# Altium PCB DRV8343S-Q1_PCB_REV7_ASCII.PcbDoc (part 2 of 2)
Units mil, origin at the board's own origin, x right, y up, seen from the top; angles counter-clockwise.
Board outline 3860 x 4000 mil, 4 copper layers (Top Layer, POWER, GND, Bottom Layer), stack 40 mil thick; 195 components, 122 nets, 548 pads, 642 vias.
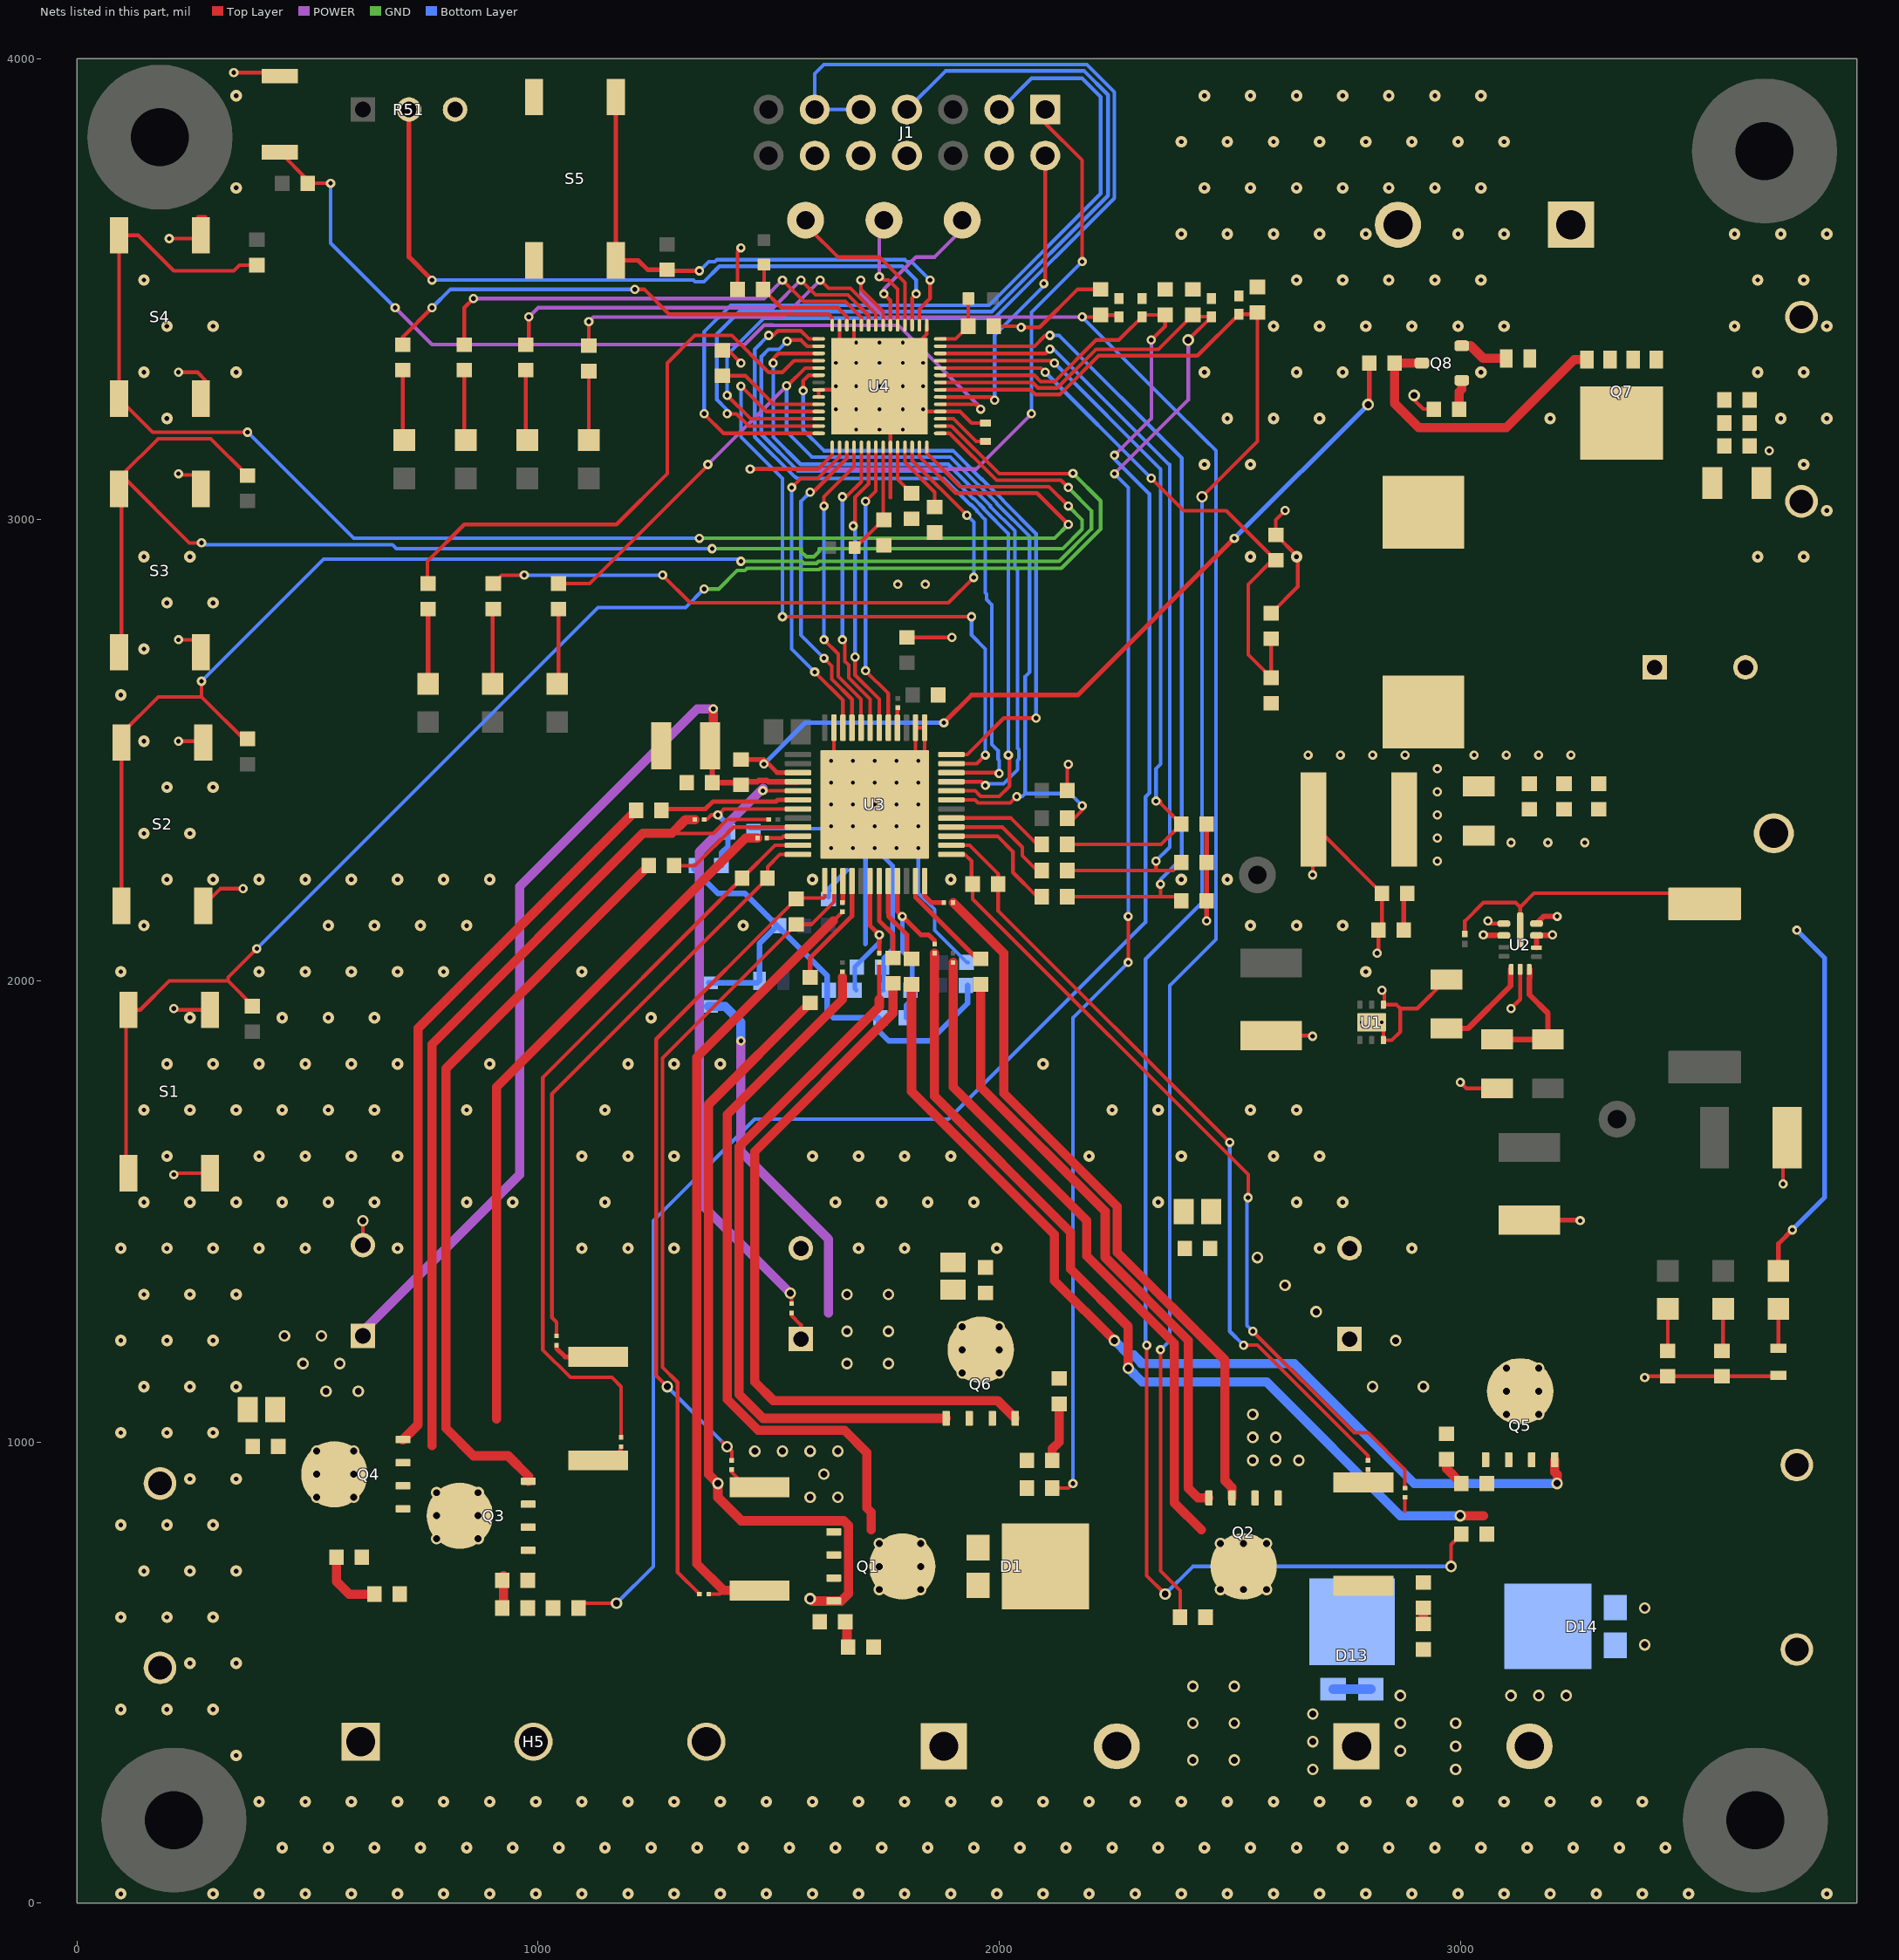
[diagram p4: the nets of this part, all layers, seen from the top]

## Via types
v1: diameter 25, hole 10, Top Layer to Bottom Layer, tented both sides, 315 vias
v2: diameter 20, hole 10, Top Layer to Bottom Layer, 173 vias
v3: diameter 25, hole 15, Top Layer to Bottom Layer, 106 vias
v4: diameter 19.68, hole 7.87, Top Layer to Bottom Layer, 32 vias
v5: diameter 19.68, hole 7.87, Top Layer to Bottom Layer, tented both sides, 16 vias

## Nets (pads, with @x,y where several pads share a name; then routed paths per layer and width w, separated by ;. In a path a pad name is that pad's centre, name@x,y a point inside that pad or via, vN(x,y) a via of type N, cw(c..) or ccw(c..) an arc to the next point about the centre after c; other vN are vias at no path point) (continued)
ENABLE: U3.36 U4.34 | length 1360.4
  Top Layer w8: v2(1574.88,3280) 1574.88,3301.59 1586.92,3313.62 U4.34@1608.5,3313.62 ; U3.36@1896.34,2491.02 1931.02,2491.02 2010,2570 v2(2080,2570)
  Bottom Layer w8: v2(1574.88,3280) 1574.88,3195.12 1620,3150 1900,3150 1961.5,3088.5 1962.52,3088.5 2008.5,3042.52 2008.5,3041.5 2080,2970 v2(2080,2570)
FB: R17.2 R18.1 U2.7 | length 278.7
  Top Layer w12: R17.2@3080,1873.15 R18.1@3190,1873.15 3190,1930 3150,1970 3150,2006.68 3150.92,2007.6 U2.7@3150.92,2024.88
GH_A: R29.1 U3.6 | length 305.5
  Top Layer w10: R29.1@1267.56,2370 1270.32,2372.76 1362.76,2372.76 1379,2389 1515.87,2389 1519.47,2392.6 U3.6@1563.66,2392.6
GH_B: R23.1 U3.19 | length 178.9
  Top Layer w10: U3.19@1739.84,2216.42 1739.84,2130.16 1770,2100 R23.1@1770,2050
GH_C: R21.1 U3.20 | length 189.7
  Top Layer w10: U3.20@1759.53,2216.42 1759.53,2147.67 1760,2147.2 1760,2140.31 1800,2100 1800,2057.56 R21.1@1810,2047.56
GL_A: R26.1 U3.9 | length 303.1
  Top Layer w8: R26.1@1295.12,2250 1340,2250 1423.54,2333.54 U3.9@1563.66,2333.54
GL_B: R20.1 U3.16 | length 246.5
  Top Layer w10: R20.1@1590,2007.56 1590,2050 1680.79,2140.79 U3.16@1680.79,2216.42
GL_C: R22.1 U3.23 | length 231.9
  Top Layer w10: U3.23@1818.58,2216.42 1818.58,2181.42 1952.44,2047.56 R22.1@1960,2047.56
GND: C7.2 C8.2 C9.2 C10.2 C11.2 C12.2 C13.2 C14.2 C15.2 C16.2 C17.2 C18.2 C19.2 C21.2 C23.2 C24.2 C27.2 C28.2 C29.2 C30.2 C31.2 C32.2 C33.2 C34.2 C36.2 C37.2 C38.2 C40.2 C41.2 C42.2 C43.2 C44.2 C45.2 C46.2 C47.2 C48.2 C49.2 C50.2 C51.2 C52.2 C53.2 C54.2 C55.2 C56.2 D14.1 D14.2 GND1.1 GND1.2 GND2.1 GND2.2 GND3.1 GND3.2 H5.1 H6.2 J1.4 J1.8 J1.10 J1.12 NT3.2 NT4.2 NT6.2 R6.1 R7.1 R11.1 R14.1 R15.1 R16.2 R17.1 R32.1 R36.1 R38.2 R44.1 R45.1 R46.1 R47.1 R51.3 R53.1 R56.1 R57.1 R59.1 R61.1 S1.3 S1.4 S2.3 S2.4 S3.3 S3.4 S4.3 S4.4 S5.3 S5.4 S6.2 U1.3 U1.4 U1.7@2807.72,1910 U2.1 U2.6 U2.11 U3.37 U3.38 U3.47 U3.49@1730,2382.76 U4.4 U4.15 U4.25 U4.27 U4.36 U4.37 U4.51 U4.57 | length 5859.3
  Top Layer w8: v2(200,3610) 261.42,3610 S4.4@268.58,3617.17 ; v2(210,1580) 212.83,1582.83 S1.3@288.58,1582.83 ; v2(210,1940) 212.83,1937.17 S1.4@288.58,1937.17 ; v2(220,2520) 270.75,2520 S2.4@273.58,2517.17 ; v2(220,2740) 270.75,2740 S3.3@273.58,2742.83 ; v2(220,3100) 222.83,3097.17 S3.4@273.58,3097.17 ; v2@222.83,3322.83 v2(220,3320) 261.42,3320 278.58,3302.83 ; 262.83,3657.17 278.58,3657.17 ; S2.3@273.58,2162.83 310.75,2200 v2(360,2200) ; v2(340,3970) 432.68,3970 S6.2@440,3962.68 ; C11.2@620,1426.85 v3(620,1480) ; C50.2@1400,3367.56 1412.44,3367.56 v2(1440,3340) ; 1420,934 1451.8,902.2 R6.1@1480,902.2 ; C56.2@1432.44,3500 1432.44,3582.44 v2(1440,3590) ; U4.37@1608.5,3266.38 U4.36@1608.5,3282.13 1638.03,3282.13 v4(1645.91,3290) ; v5(1635.51,2477.24) 1641.42,2483.15 U3.47@1641.42,2549.09 ; U4.57@1653.78,3376.61 U4.27@1653.78,3421.89 ; U4.25@1685.28,3421.89 1685.28,3389.21 v4(1690,3384.49) ; v4(1730,2382.76) v4(1777.24,2430) v5(1824.49,2477.24) 1838.27,2491.02 U3.37@1838.27,2549.09 U3.38@1818.58,2549.09 U3.49@1818.58,2483.15 ; v4(1740.39,3290) 1740.39,3300.39 1842.76,3402.76 U4.15@1842.76,3421.89 ; 1764.02,3048.43 U4.51@1764.02,3158.11 U4.57@1764.02,3266.38 ; C41.2@1800,2745.12 1857.56,2745.12 ; v4(1834.88,3239.61) 1839.61,3234.88 U4.4@1872.28,3234.88 1915.12,3234.88 1940,3210 C47.2@1970,3210 ; 1850,2745.12 v2(1897.56,2745.12) ; C51.2@1987.95,3420 2050,3420 v2(2047.5,3417.5) 2087.5,3417.5 2169.68,3499.68 R44.1@2220,3499.68 ; C34.2@2147.56,2412.76 2147.56,2467.56 v2(2150,2470) ; C18.2@2590,1881.26 2678.74,1881.26 v2(2680,1880) ; R32.1@2590,2797.56 2647.56,2855.12 2647.56,2920 C42.2@2600,2967.56 2600,3000 v2(2620,3020) ; v2(2680,2230) 2680,2348.43 C28.2@2681.57,2350 2681.57,2338.43 C24.2@2830,2190 2830,2117.56 C21.2@2822.44,2110 2822.44,2062.44 v2(2820,2060) ; R7.1@2790,912.2 2800,922.2 NT4.2@2800,940 ; v4(2829.37,1910) 2833.31,1906.06 U1.3@2833.31,1871.61 ; v2(2830,1980) 2835.59,1974.41 2835.59,1948.39 2861.61,1948.39 2870,1940 ; U1.3@2835.59,1871.61 2851.61,1871.61 2870,1890 2870,1940 ; v3(2900,3270) 2900,3260 2920,3240 R38.2@2942.44,3240 ; C19.2@2970,2003.15 2906.85,1940 2870,1940 ; v2(3000,1780) 3013.15,1766.85 R17.1@3080,1766.85 ; v2(3060,2130) 3065.71,2124.29 U2.1@3094.57,2124.29 ; v2(3110,1940) 3130,1960 U2.6@3130,2024.88 ; v2(3400,1140) 3402.44,1142.44 R14.1@3450,1142.44 R15.1@3567.54,1142.44 3688.03,1142.44 R16.2@3690,1144.41 ; v2(3700,1560) 3700,1651.26 C17.2@3708.74,1660
  Top Layer w10: 1040,1203 1058.59,1184.41 R11.1@1130,1184.41 ; v2(2450,2130) C23.2@2450,2173.91 C27.2@2450,2256.96 C30.2@2450,2340 ; C15.2@3150,1481.26 3258.74,1481.26 v2(3260,1480)
  Top Layer w12: U2.11@3165.43,2124.29 3181.14,2140 v2(3210,2140)
  Bottom Layer w8: R61.1@1459.37,2330 1471.18,2330 1630,2330 v5(1635.51,2335.51) ; v5(1824.49,2288.27) 1824.49,2190.39 1860,2154.88 1860,2110 1930,2040 R57.1@1932.99,2040
  Bottom Layer w10: R59.1@1630,2181.5 1630,2200 1670,2240 ; 1709.69,2080 1710,2080.31 1710,2270 ; v5(1730,2288.27) 1769,2249.27 1769,2069 1750,2050 1750,2030 1750,1981.5 R53.1@1748.5,1980
  other v1: 95,20 295,20 395,20 495,20 595,20 695,20 795,20 895,20 995,20 1095,20 1195,20 1295,20 1395,20 1495,20 1595,20 1695,20 1795,20 1895,20 1995,20 2095,20 2195,20 2295,20 2395,20 2495,20 2595,20 2695,20 2795,20 2895,20 2995,20 3095,20 3195,20 3295,20 3395,20 3495,20 3795,20 445,120 545,120 645,120 745,120 845,120 945,120 1045,120 1145,120 1245,120 1345,120 1445,120 1545,120 1645,120 1745,120 1845,120 1945,120 2045,120 2145,120 2245,120 2345,120 2445,120 2545,120 2645,120 2745,120 2845,120 2945,120 3045,120 3145,120 3245,120 3345,120 3445,120 395,220 495,220 595,220 695,220 795,220 895,220 995,220 1095,220 1195,220 1295,220 1395,220 1495,220 1595,220 1695,220 1795,220 1895,220 1995,220 2095,220 2195,220 2295,220 2395,220 2495,220 2595,220 2695,220 2795,220 2895,220 2995,220 3095,220 3195,220 3295,220 3395,220 345,320 95,420 195,420 295,420 245,520 345,520 95,620 195,620 295,620 145,720 245,720 345,720 95,820 195,820 295,820 245,920 345,920 95,1020 195,1020 295,1020 145,1120 245,1120 345,1120 95,1220 195,1220 295,1220 145,1320 245,1320 345,1320 95,1420 195,1420 295,1420 395,1420 495,1420 695,1420 1095,1420 1195,1420 1295,1420 1695,1420 1795,1420 1995,1420 2695,1420 2895,1420 145,1520 245,1520 345,1520 445,1520 545,1520 645,1520 845,1520 945,1520 1145,1520 1645,1520 1745,1520 1845,1520 1945,1520 2345,1520 2645,1520 2745,1520 195,1620 395,1620 495,1620 595,1620 695,1620 1095,1620 1195,1620 1295,1620 1595,1620 1695,1620 1795,1620 1895,1620 2195,1620 2395,1620 2595,1620 2695,1620 145,1720 245,1720 345,1720 445,1720 545,1720 645,1720 845,1720 1145,1720 2245,1720 2345,1720 2545,1720 2645,1720 195,1820 295,1820 395,1820 495,1820 595,1820 695,1820 895,1820 1195,1820 1295,1820 1395,1820 2095,1820 245,1920 445,1920 545,1920 645,1920 1245,1920 95,2020 395,2020 495,2020 595,2020 695,2020 795,2020 1095,2020 2795,2020 145,2120 545,2120 645,2120 745,2120 845,2120 1445,2120 2545,2120 2645,2120 2745,2120 195,2220 295,2220 395,2220 495,2220 595,2220 695,2220 795,2220 895,2220 1595,2220 1895,2220 2395,2220 2495,2220 145,2320 245,2320 195,2420 295,2420 145,2520 95,2620 145,2720 195,2820 295,2820 145,2920 245,2920 2545,2920 2645,2920 3645,2920 3745,2920 3795,3020 2445,3120 2545,3120 3745,3120 195,3220 2495,3220 2595,3220 2695,3220 3195,3220 3695,3220 3795,3220 145,3320 345,3320 2445,3320 2645,3320 2745,3320 3045,3320 3645,3320 3745,3320 195,3420 295,3420 2595,3420 2695,3420 2795,3420 2895,3420 2995,3420 3095,3420 3595,3420 3795,3420 145,3520 2645,3520 2745,3520 2845,3520 2945,3520 3045,3520 3645,3520 3745,3520 2395,3620 2495,3620 2595,3620 2695,3620 2795,3620 2995,3620 3095,3620 3595,3620 3695,3620 3795,3620 345,3720 2445,3720 2545,3720 2645,3720 2745,3720 2845,3720 2945,3720 3045,3720 2395,3820 2495,3820 2595,3820 2695,3820 2795,3820 2895,3820 2995,3820 3095,3820 345,3920 2445,3920 2545,3920 2645,3920 2745,3920 2845,3920 2945,3920 3045,3920
  other v2: 3110,2300 3190,2300 3270,2300 1780,2860 1840,2860 3670,3150
  other v3: 3400,560 3400,640 1590,880 1650,880 1620,930 2550,960 2600,960 2650,960 1470,980 1530,980 1590,980 1650,980 2550,1010 2600,1010 2550,1060
  other v4: 2786.06,1910 1682.76,2335.51 1730,2335.51 1777.24,2335.51 1682.76,2382.76 1777.24,2382.76 1682.76,2430 1730,2430 1690,3195.51 1740.39,3195.51 1790.79,3195.51 1645.91,3239.61 1690,3239.61 1740.39,3239.61 1790.79,3239.61 1690,3290 1790.79,3290 1834.88,3290 1645.91,3340.39 1690,3340.39 1740.39,3340.39 1790.79,3340.39 1834.88,3340.39 1740.39,3384.49 1790.79,3384.49
  other v5: 1635.51,2288.27 1682.76,2288.27 1777.24,2288.27 1824.49,2335.51 1635.51,2382.76 1824.49,2382.76 1635.51,2430 1824.49,2430 1682.76,2477.24 1730,2477.24 1777.24,2477.24
INH_A: U3.41 U4.49 | length 638.9
  Top Layer w8: v2(1710,2672.72) 1759.53,2623.19 U3.41@1759.53,2549.09 ; v2(1710,3040) 1732.52,3062.52 U4.49@1732.52,3158.11
  Bottom Layer w8: v2(1710,2672.72) v2(1710,3040)
INH_B: U3.43 U4.47 | length 655.8
  Top Layer w8: v2(1660,2740) 1665,2735 1665,2693.18 1673.5,2684.68 1673.5,2657.6 1720.16,2610.94 U3.43@1720.16,2549.09 ; v2(1660,3050) 1668.38,3050 1701.02,3082.64 U4.47@1701.02,3158.11
  Bottom Layer w8: v2(1660,2740) v2(1660,3050)
INH_C: U3.45 U4.45 | length 700
  Top Layer w8: v2(1590,3060) 1596.54,3060 1669.53,3132.99 U4.45@1669.53,3158.11 ; v2(1620,2700) 1637,2683 1637,2654.5 1680.79,2610.71 U3.45@1680.79,2549.09
  Bottom Layer w8: v2(1590,3060) 1570,3040 1570,2750 v2(1620,2700)
INL_A: U3.42 U4.48 | length 646.3
  Top Layer w8: v2(1683.34,2986.66) 1687.5,2990.82 1687.5,3049.32 1716.77,3078.59 U4.48@1716.77,3158.11 ; v2(1687.5,2702.5) 1687.5,2663.4 1739.84,2611.05 U3.42@1739.84,2549.09
  Bottom Layer w8: v2(1683.34,2986.66) 1687.5,2982.5 v2(1687.5,2702.5)
INL_B: U3.44 U4.46 | length 669.4
  Top Layer w8: v2(1620,2740) 1651,2709 1651,2660.3 1700.47,2610.83 U3.44@1700.47,2549.09 ; v2(1620,3030) 1620,3050 1685.28,3115.28 U4.46@1685.28,3158.11
  Bottom Layer w8: v2(1620,2740) v2(1620,3030)
INL_C: U3.46 U4.44 | length 719.5
  Top Layer w8: v2(1550,3070) 1570,3090 1606.74,3090 1653.78,3137.04 U4.44@1653.78,3158.11 ; v2(1600,2670) 1661.1,2608.9 U3.46@1661.1,2549.09
  Bottom Layer w8: v2(1550,3070) 1550,2720 v2(1600,2670)
ISEN_A: C30.1 R27.1 U4.11 | length 1643.3
  Top Layer w8: U4.11@1872.28,3345.12 2114.88,3345.12 v2(2120,3340) ; R27.1@2147.56,2296.09 2350.97,2296.09 C30.1@2394.88,2340 2350,2384.88 2350,2390 v2(2340,2390)
  Bottom Layer w8: v2(2120,3340) 2350,3110 2350,2470 2340,2460 v2(2340,2390)
ISEN_B: C27.1 R25.1 U4.12 | length 1752.6
  Top Layer w8: U4.12@1872.28,3360.87 2100.87,3360.87 v2(2110,3370) ; R25.1@2147.56,2239.42 2340,2239.42 ; v2(2340,2260) 2340,2239.42 ; C27.1@2394.88,2256.96 2377.35,2239.42 2340,2239.42
  Bottom Layer w8: v2(2110,3370) 2118.28,3370 2368.28,3120 2370,3120 2370,2290 v2(2340,2260)
ISEN_C: C23.1 R24.1 U4.13 | length 1864.9
  Top Layer w8: U4.13@1872.28,3376.61 2076.61,3376.61 2100,3400 v2(2110,3400) ; R24.1@2147.56,2182.76 2350,2182.76 ; v2(2350,2210) 2350,2182.76 ; C23.1@2394.88,2173.91 2386.04,2182.76 2350,2182.76
  Bottom Layer w8: v2(2110,3400) 2130,3400 2396,3134 2396,2266 2350,2220 v2(2350,2210)
NetC15_1: C37.1 C45.1 C46.1 C48.1 C49.1 L2.1 Q7.5
NetC47_1: C6.1 R13.1 | length 128.6
  Top Layer w20: C6.1@2115.12,960 2115.12,985.12 2130,1000 R13.1@2130,1082.44
NetC48_1: C5.1 R12.1 | length 65.9
  Top Layer w20: R12.1@2970,962.44 2970,942.44 C5.1@3002.44,910
NetC49_1: C3.1 R8.1 | length 146.3
  Top Layer w20: R8.1@562.44,750 562.44,697.56 590,670 C3.1@644.88,670
NetC50_1: C4.1 R4.1 | length 61
  Top Layer w20: R4.1@922.44,650 924.88,652.44 C4.1@924.88,710
NetC50_2: C4.2 NT5.2 NT14.2 Q3.1 Q3.2 Q3.3 R11.2 | length 1569.6
  Top Layer w8: R11.2@1130,960 1156,960 1180,984
  Top Layer w20: 910,1050 910,1770 1450,2310 NT14.2@1476,2310
NetC51_1: C2.1 R1.1 | length 34.9
  Top Layer w20: R1.1@2920,605.12 C2.1@2920,640
NetC51_2: C2.2 NT2.2 NT13.2 Q2.1 Q2.2 Q2.3 R7.2 | length 1571.9
  Top Layer w8: 2880,850 NT2.2@2880,880
  Top Layer w20: NT13.2@1900,2170 2010,2060 2010,1756.77 2256,1510.77 2256,1411.08 2490,1177.08 2490,916 2505,901 Q2.3@2505,878.65
NetC52_1: C1.1 R2.1 | length 57.5
  Top Layer w20: C1.1@1666.15,609.92 1670,606.07 1670,557.44 R2.1@1672.44,555
NetC52_2: C1.2 NT1.2 NT12.2 Q1.1 Q1.2 Q1.3 R6.2 | length 1740.3
  Top Layer w8: NT1.2@1370,670 1394.41,670 1402.2,677.8 ; 1640.24,2130 NT12.2@1660,2149.76
  Top Layer w20: R6.2@1480,677.8 1402.2,677.8 1344,736 1344,1834 1640,2130 1640.24,2130
NetD1_2: D4.2 R16.1 | length 85.2
  Top Layer w8: R16.1@3690,1203.46 D4.2@3690,1288.66
NetD2_2: D8.2 R40.2 | length 153.6
  Top Layer w8: R40.2@706.67,3324.88 706.67,3176.01 D8.2@710,3172.68
NetD3_2: D3.2 R15.2 | length 92.1
  Top Layer w8: R15.2@3567.54,1197.56 3570,1200.02 D3.2@3570,1288.66
NetD4_2: D9.2 R41.2 | length 153.6
  Top Layer w8: R41.2@840,3324.88 840,3176.01 D9.2@843.33,3172.68
NetD5_2: D2.2 R14.2 | length 91.1
  Top Layer w8: R14.2@3450,1197.56 D2.2@3450,1288.66
NetD6_2: D10.2 R42.2 | length 153.6
  Top Layer w8: R42.2@973.33,3324.88 973.33,3176.01 D10.2@976.67,3172.68
NetD7_2: D7.2 R35.2 | length 163.6
  Top Layer w8: D7.2@1041.37,2644.19 1044.1,2646.92 R35.2@1044.1,2806.63
NetD8_2: D11.2 R39.2 | length 149.8
  Top Layer w8: D11.2@1110,3172.68 R39.2@1110,3322.44
NetD9_2: D5.2 R33.2 | length 162.4
  Top Layer w10: D5.2@761.37,2644.19 R33.2@761.37,2806.63
NetD10_2: D6.2 R34.2 | length 163
  Top Layer w8: D6.2@901.37,2644.19 901.37,2805.26 R34.2@902.73,2806.63
NetD12_2: D12.2 Q8.2 | length 108
  Top Layer w20: Q8.2@3003.31,3377.4 3022.6,3377.4 3050,3350 D12.2@3100,3350
NetQ1_1: Q8.1 R38.1 | length 65
  Top Layer w20: R38.1@2997.56,3240 2997.56,3277.56 3003.31,3283.31 Q8.1@3003.31,3302.6
NetQ1_3: Q7.4 Q8.3 R43.2 | length 646.9
  Top Layer w20: Q8.3@2916.69,3340 R43.2@2857.56,3340 2857.56,3252.44 2910,3200 3100,3200 3247.5,3347.5 Q7.4@3275,3347.5
NetQ3_4: Q4.4 R29.2 | length 1574.4
  Top Layer w20: Q4.4@706.89,1005 740,1038.11 740,1897.56 R29.2@1212.44,2370
NetQ4_4: Q6.4 R23.2 | length 1586.7
  Top Layer w20: R23.2@1770,1994.88 1770,1930 1470,1630 1470,1130 1510,1090 1996.35,1090 Q6.4@2035,1051.35
NetQ5_4: Q5.4 R21.2 | length 2097.6
  Top Layer w20: R21.2@1810,1992.44 1810,1760 2120,1450 2120,1350 v3(2250,1220) ; Q5.4@3205,961.35 3205,935 3210,930 v3(3210,910)
  Bottom Layer w20: v3(2250,1220) 2281.5,1188.5 2291.81,1188.5 2308.5,1171.8 2308.5,1170 2640,1170 2900,910 v3(3210,910)
NetQ6_4: Q3.4 R26.2 | length 1636.3
  Top Layer w20: Q3.4@978.65,915 980,916.35 980,925 935,970 860,970 800,1030 800,1810 R26.2@1240,2250
NetQ7_4: Q2.4 R22.2 | length 1332.7
  Top Layer w20: R22.2@1960,1992.44 1960,1770 2230,1500 2230,1400.31 2410,1220.31 2410,900 2431.35,878.65 Q2.4@2455,878.65
NetQ8_4: Q1.4 R20.2 | length 1720.6
  Top Layer w20: v3(1590,660) 1595,655 Q1.4@1641.35,655 1657.51,655 1673.49,670.98 1673.49,818.56 1662.98,829.07 1440.93,829.07 1390,880 v3(1390,910) 1370,930 1370,1732.44 R20.2@1590,1952.44
NetR7_2: R36.2 U4.53 | length 157.3
  Top Layer w8: U4.53@1795.51,3158.11 1795.51,3124.49 1860,3060 R36.2@1860,3027.56
NetR24_2: R24.2 U3.27 | length 266.7
  Top Layer w8: U3.27@1896.34,2313.86 1996.14,2313.86 2030,2280 2030,2235.2 R24.2@2082.44,2182.76
NetR25_2: R25.2 U3.28 | length 235.7
  Top Layer w8: U3.28@1896.34,2333.54 2006.46,2333.54 2050,2290 2050,2271.86 R25.2@2082.44,2239.42
NetR26_2: R27.2 U3.29 | length 209.8
  Top Layer w8: U3.29@1896.34,2353.23 2025.3,2353.23 R27.2@2082.44,2296.09
NetTP1_1: AI1.1 U4.18 | length 356
  Top Layer w8: AI1.1@1580,3630 1590,3630 1650,3570 1740,3570 1795.51,3514.49 U4.18@1795.51,3421.89
NetTP2_1: AI2.1 U4.19 | length 239.6
  Top Layer w8: v2(1740,3527.5) 1740,3530 1750,3520 1760,3520 1779.76,3500.24 U4.19@1779.76,3421.89
  POWER w8: v2(1740,3527.5) AI2.1@1740,3620
  GND w8: AI2.1@1740,3620 AI2.1@1750,3630
NetTP3_1: AI3.1 U4.20 | length 307.8
  Top Layer w8: v2(1750,3490) 1764.02,3475.98 U4.20@1764.02,3421.89
  POWER w8: v2(1750,3490) 1750,3500 1820,3570 1860,3570 AI3.1@1920,3630
nFAULT: R28.1 R35.1 U3.31 U4.33 | length 2408.4
  Top Layer w8: R35.1@1044.1,2861.75 1111.75,2861.75 1368.18,3118.18 v2(1368.18,3120) ; v2(1539.09,3290.91) 1540,3290 1579.37,3329.37 U4.33@1608.5,3329.37 ; U3.31@1896.34,2392.6 1947.6,2392.6 1954.2,2386 2024,2386 v2(2038,2400) ; R28.1@2137.56,2352.76 R28.1@2147.56,2352.76 2162.76,2352.76 2180,2370 v2(2180,2380)
  POWER w8: v2(1368.18,3120) v2(1539.09,3290.91)
  Bottom Layer w8: v2(1539.09,3290.91) 1539.09,3190.91 1594,3136 1894,3136 1955.5,3074.5 1956.72,3074.5 1994.5,3036.72 1994.5,3035.5 2066,2964 2066,2670 2056.5,2660.5 2056.5,2406.5 ; v2(2038,2400) 2050,2400 2056.5,2406.5 ; v2(2180,2380) 2153.5,2406.5 2056.5,2406.5
nRESET: R50.1 S6.1 U4.5 | length 1960.6
  Top Layer w8: S6.1@440,3797.32 500,3737.32 R50.1@500,3730 v2(550,3730) ; U4.5@1872.28,3250.63 1949.37,3250.63 v2(1960,3240)
  POWER w8: v2(690,3460) 770,3380 1448.18,3380 1490.68,3422.5 1509.32,3422.5 1509.93,3421.89 1781.45,3421.89 1960,3243.34 v2(1960,3240)
  Bottom Layer w8: v2(550,3730) 550,3600 v2(690,3460)
nSCS: U3.35 U4.39 | length 1532.4
  Top Layer w8: v2(1440,3290) 1495.12,3234.88 U4.39@1608.5,3234.88 ; v2(1530,2790) 1570,2790 v2(1940,2790) ; U3.35@1896.34,2471.34 1951.34,2471.34 v2(1970,2490)
  Bottom Layer w8: v2(1440,3290) 1440,3180 1530,3090 v2(1530,2790) ; v2(1940,2790) 1940,2750 1970,2720 v2(1970,2490)
OL: R48.1 S5.1 S5.2 U4.16 | length 1181
  Top Layer w8: U4.16@1827.01,3421.89 1827.01,3457.01 1850,3480 v2(1850,3520)
  Top Layer w10: S5.1@1168.58,3917.17 S5.2@1168.58,3562.83 1217.17,3562.83 1237.56,3542.44 R48.1@1280,3542.44 1282.44,3540 v2(1350,3540)
  Bottom Layer w8: v2(1350,3540) 1370,3560 1383.44,3560 1387.44,3564 1795.8,3564 1799.8,3560 1810,3560 v2(1850,3520)
OUT_A1: C3.2 H5.2 NT15.2 NT16.2 Q3.5 Q4.1 Q4.2 Q4.3 R4.2 R5.2 | length 1864.8
  Top Layer w8: 1290,2320 1380,2320 1410,2350 NT16.2@1500,2350
  Top Layer w20: 770,992.16 770,1862.67 1227.33,2320 1290,2320 1320,2350 NT15.2@1340,2350
  other v3: 780,790 870,790 780,840 870,840 780,890 870,890
OUT_B1: C6.2 D1.3 H1.2 NT9.2 Q6.1 Q6.2 Q6.3 R10.2 | length 1526.1
  Top Layer w10: 1740,1960 1740,2033
  Top Layer w20: 1740,1960 1740,1944 1436,1640 1436,1103.38 1488.04,1051.35 Q6.1@1885,1051.35
OUT_B2: D1.1 D1.2 H1.1 NT8.2 Q1.5 R2.2 | length 1540.7
  Top Layer w20: 1660,2008 1660,1960 1410,1710 1410,1092.62 1477.27,1025.35 1664.65,1025.35 1713.31,976.69 1713.31,856.69 1722.25,847.75 1722.25,809.94
  other v3: 1740,680 1830,680 1740,730 1830,730 1740,780 1830,780
OUT_C1: C5.2 D14.3 H2.2 NT11.2 Q5.1 Q5.2 Q5.3 R9.2 | length 1976.5
  Top Layer w20: NT11.2@1860,2060 1860,1750 2155,1455 2155,1375 2280,1250 v3(2280,1160) ; v3(3000,840) 3050,840
  Bottom Layer w20: v3(2280,1160) 2310,1130 2580,1130 2870,840 v3(3000,840)
  other v3: 2990,290 2990,340 2990,390 3110,450 3170,450 3230,450
OUT_C2: D13.1 D13.2 H2.1 NT10.2 Q2.5 R1.2 R3.2 | length 1535.4
  Top Layer w20: NT10.2@1900,2040 1900,1770 2190,1480 2190,1403.54 2380,1213.54 2380,867.8 2438.35,809.46
  Bottom Layer w20: D13.1@2724.27,463.84 D13.2@2806.16,463.84
  other v3: 2680,290 2870,330 2680,350 2870,390 2680,410 2870,450 2480,680 2530,680 2580,680 2480,780 2530,780 2580,780
PB_A: R49.1 S4.1 S4.2 U4.55 | length 3291.4
  Top Layer w8: v2(370,3190) 164.25,3190 S4.1@91.42,3262.83 S4.2@91.42,3617.17 132.83,3617.17 210,3540 340,3540 352.44,3552.44 R49.1@390,3552.44 ; U4.55@1827.01,3158.11 1827.01,3137.04 1906.05,3058 2082,3058 v2(2150,2990)
  GND w8: v2(1350,2960) 2120,2960 v2(2150,2990)
  Bottom Layer w8: v2(370,3190) 600,2960 v2(1350,2960)
PB_B: R37.1 S3.1 S3.2 U4.56 | length 3313.2
  Top Layer w8: S3.1@96.42,2742.83 S3.2@96.42,3097.17 ; v2(270,2950) 243.58,2950 S3.2@96.42,3097.17 ; R37.1@370,3096.06 290.06,3176 176,3176 97.17,3097.17 S3.2@96.42,3097.17 ; U4.56@1842.76,3158.11 1842.76,3144.59 1915.35,3072 2108,3072 v2(2150,3030)
  GND w8: v2(1377.5,2937.5) 1570,2937.5 1570,2931.72 1581.72,2920 1598.28,2920 1610,2931.72 1610,2937.5 2137.9,2937.5 2180,2979.6 2180,3000 v2(2150,3030)
  Bottom Layer w8: v2(270,2950) 274,2946 684,2946 692.5,2937.5 v2(1377.5,2937.5)
PB_CH: R30.1 S2.1 S2.2 U4.1 | length 3266.9
  Top Layer w8: S2.1@96.42,2162.83 S2.2@96.42,2517.17 96.42,2536.42 176.06,2616.06 270,2616.06 ; v2(270,2650) 270,2616.06 ; R30.1@370,2516.06 270,2616.06 ; U4.1@1872.28,3187.64 1892.56,3187.64 1994.2,3086 2134,3086 v2(2150,3070)
  GND w8: v2(1440,2910) 1571.92,2910 1575.92,2906 1604.08,2906 1608.08,2910 2130.2,2910 2200,2979.8 2200,3020 v2(2150,3070)
  Bottom Layer w8: v2(270,2650) 535,2915 1435,2915 v2(1440,2910)
PB_CL: R19.1 S1.1 S1.2 U4.2 | length 3465.4
  Top Layer w8: S1.1@106.42,1582.83 106.42,1937.17 S1.2@111.42,1937.17 137.17,1937.17 200,2000 327.61,2000 ; R19.1@385,1942.61 327.61,2000 ; v2(390,2070) 327.61,2007.61 327.61,2000 ; U4.2@1872.28,3203.39 1896.61,3203.39 2000,3100 2160,3100 v2(2160,3101)
  GND w8: v2(1360,2850) 1391.72,2850 1431.72,2890 1448.28,2890 1451.28,2893 1451.89,2893.57 1452.04,2893.57 1452.55,2894.08 1452.79,2894.08 1453.24,2894.53 1453.59,2894.53 1453.98,2894.92 1454.43,2894.92 1454.51,2895 1567.12,2895 1570.12,2892 1609.88,2892 1612.88,2895 2135,2895 2220,2980 2220,3041 v2(2160,3101)
  Bottom Layer w8: v2(390,2070) 1130,2810 1320,2810 v2(1360,2850)
POT: R51.2 U4.17 | length 1557.8
  Top Layer w8: U4.17@1811.26,3421.89 1811.26,3481.26
  Top Layer w10: R51.2@720,3890 720,3570 v2(770,3520)
  Bottom Layer w8: v2(770,3520) 1336.77,3520 1340.27,3516.5 1359.73,3516.5 1393.23,3550 1790,3550 1820,3520 v2(1820,3490)
RESDIV: D15.1 D16.1 R52.2 R54.2 R55.2 R58.2 R60.2 | length 1138.1
  Bottom Layer w12: R60.2@1338.5,2250 1338.5,2241.5 1390,2190 1448.5,2190 R58.2@1518.5,2120 ; D15.1@1370,1995.59 1475.59,1995.59 D16.1@1480,2000 1480,2081.5 R58.2@1518.5,2120 ; R55.2@1931.5,1990 1931.5,1951.5 1850,1870 1760,1870 1738.5,1891.5 1738.5,1920 1640,1920 1627.01,1932.99 1627.01,2011.5 R58.2@1518.5,2120
SCK: U3.34 U4.29 | length 1594.8
  Top Layer w8: v2(1500,3400) 1510,3400 1520,3410 1570,3410 1587.64,3392.36 U4.29@1608.5,3392.36 ; U3.34@1896.34,2451.65 1998.35,2451.65 v2(2000,2450)
  Bottom Layer w8: v2(1500,3400) 1470,3370 1470,3180 1557.5,3092.5 1559.32,3092.5 1561.82,3090 1880.2,3090 1937.7,3032.5 1939.32,3032.5 1952.5,3019.32 1952.5,3017.7 1970,3000.2 1970,2841.82 1972.5,2839.32 1972.5,2827.3 1984,2815.8 1984,2512.82 1997.5,2499.32 1997.5,2480.68 2000,2478.18 v2(2000,2450)
SDI: U3.33 U4.31 | length 1566.1
  Top Layer w8: v2(1510,3340) 1510,3350 1520.87,3360.87 U4.31@1608.5,3360.87 ; U3.33@1896.34,2431.97 1961.97,2431.97 v2(1970,2423.94)
  Bottom Layer w8: v2(1510,3340) 1510,3179.6 1569.1,3120.5 1889.5,3120.5 1949.5,3060.5 1950.92,3060.5 1980.5,3030.92 1980.5,3029.5 2034,2976 2034,2896 2040,2890 2040,2504.32 2042.5,2501.82 2042.5,2480.68 2040,2478.18 2040,2458.18 2009.32,2427.5 1973.56,2427.5 v2(1970,2423.94)
SDO: U3.32 U4.30 | length 1630.1
  Top Layer w8: v2(1540,3387.5) 1540,3390 1570,3390 1583.39,3376.61 U4.30@1608.5,3376.61 ; U3.32@1896.34,2412.28 1947.72,2412.28 1960,2400 2000,2400 2022.5,2422.5 2022.5,2487.5 v2(2020,2490)
  Bottom Layer w8: v2(1540,3387.5) 1522.5,3370 1500,3370 1484,3354 1484,3185.8 1563.3,3106.5 1883.5,3106.5 1943.5,3046.5 1945.12,3046.5 1966.5,3025.12 1966.5,3024.1 1966.5,3023.5 2020,2970 v2(2020,2490)
SH_A: NT15.1 R60.1 R61.2 U3.7 | length 332.1
  Top Layer w8: 1366,2350 1376,2360 v2(1390,2360) 1402.91,2372.91 U3.7@1563.66,2372.91
  Bottom Layer w12: v2(1390,2360) 1411.84,2338.16 R61.2@1411.84,2323.74 1411.84,2291.84 1397.56,2277.56 R60.1@1397.56,2250
SH_B: NT9.1 R54.1 R56.2 U3.18 | length 307.8
  Top Layer w10: U3.18@1720.16,2216.42 1720.16,2119.84 v2(1740,2100) NT9.1@1740,2060
  Bottom Layer w10: R54.1@1690,1980 1687.01,1982.99 1687.01,2030 1740,2082.99 v2(1740,2100)
SH_C: NT11.1 R52.1 R53.2 U3.21 | length 405.9
  Top Layer w10: U3.21@1779.21,2216.42 1779.21,2150.79 v2(1790,2140) 1830,2100 1847,2100 1860,2087
  Bottom Layer w10: v2(1790,2140) 1790,2063.91 1811.5,2042.41 R53.2@1811.5,1980 ; R52.1@1797.56,1920 1797.56,1947.56 1807.56,1957.56 R53.2@1807.56,1980
SL_A: NT14.1 U3.10 | length 69.3
  Top Layer w8: NT14.1@1496,2310 1528.59,2310 1532.45,2313.86 U3.10@1563.66,2313.86
SL_B: NT12.1 U3.15 | length 47.1
  Top Layer w10: NT12.1@1660,2169.76 1661.1,2170.86 U3.15@1661.1,2216.42
SL_C: NT13.1 U3.24 | length 72.7
  Top Layer w10: U3.24@1838.27,2216.42 1838.27,2184.36 1852.63,2170 1873,2170
SN_A: C26.2 NT6.1 U3.12 | length 1292.6
  Top Layer w8: NT6.1@1040,1230 1040,1259.8 1030,1269.8 1030,1755.2 C26.2@1497.56,2222.76 1497.56,2247.56 1524.49,2274.49 U3.12@1563.66,2274.49
SN_B: C22.2 NT3.1 U3.13 | length 1524
  Top Layer w8: v3(1280,1120) 1256,1144 1256,1873.87 C22.2@1560,2177.87 1561.88,2179.76 1620,2179.76 1621.73,2181.49 U3.13@1621.73,2216.42 ; 1400,1000 v3(1410,990) 1420,980 NT3.1@1420,960
  Bottom Layer w8: v3(1280,1120) v3(1410,990)
SN_C: C25.2 NT4.1 U3.26 | length 1749.2
  Top Layer w8: U3.26@1896.34,2294.17 1935.83,2294.17 1997.56,2232.44 C25.2@1997.56,2210 1997.56,2152.44 v2(2500,1650) ; v2(2530,1210) 2560,1210 2800,970 NT4.1@2800,960
  Bottom Layer w8: v2(2500,1650) 2500,1240 v2(2530,1210)
SP_A: C26.1 NT5.1 U3.11 | length 1665.8
  Top Layer w8: NT5.1@1180,1010 1180,1120 1160,1140 1070,1140 1010,1200 1010,1790.32 C26.1@1442.44,2222.76 1513.86,2294.17 U3.11@1563.66,2294.17
SP_B: C22.1 NT1.1 U3.14 | length 1752.7
  Top Layer w8: NT1.1@1350,670 1302.5,717.5 1302.5,1129.32 1270,1161.82 1270,1832.76 C22.1@1560,2122.76 1593,2122.76 1641.42,2171.17 U3.14@1641.42,2216.42
SP_C: C25.1 NT2.1 U3.25 | length 1815.1
  Top Layer w8: U3.25@1896.34,2274.49 1925.51,2274.49 1940,2260 1940,2212.44 C25.1@1942.44,2210 1942.44,2177.56 2540,1580 v2(2540,1530) ; v2(2550,1240) 2770,1020 2800,1020 2880,940 NT2.1@2880,900
  Bottom Layer w8: v2@2537.5,1527.5 2537.5,1252.5 v2(2550,1240)
STATUS_A: R40.1 U4.28 | length 1032.6
  Top Layer w8: R40.1@706.67,3380 706.67,3396.67 v2(770,3460) ; v2(1210,3500) 1230,3500 1284,3446 1630,3446 1638.03,3437.97 U4.28@1638.03,3421.89
  Bottom Layer w8: v2(770,3460) 810,3500 v2(1210,3500)
STATUS_B: R41.1 U4.24 | length 1016.5
  Top Layer w8: R41.1@840,3380 840,3460 v2(860,3480) ; v2(1530,3520) 1576,3474 1666,3474 1701.02,3438.98 U4.24@1701.02,3421.89
  POWER w8: v2(860,3480) 1490,3480 v2(1530,3520)
STATUS_CH: R42.1 U4.23 | length 885.7
  Top Layer w8: R42.1@973.33,3380 980,3386.67 v2(980,3440) ; v2(1570,3520) 1602,3488 1671.8,3488 1716.77,3443.03 U4.23@1716.77,3421.89
  POWER w8: v2(980,3440) 1000,3460 1510,3460 v2(1570,3520)
STATUS_CL: R39.1 U4.22 | length 767.6
  Top Layer w8: R39.1@1110,3377.56 v2(1110,3430) ; v2(1612,3520) 1630,3502 1677.6,3502 1732.52,3447.08 U4.22@1732.52,3421.89
  POWER w8: v2(1110,3430) 1120,3440 1532,3440 v2(1612,3520)
STATUS_MCU1: R33.1 U4.32 | length 1284.4
  Top Layer w8: R33.1@761.37,2861.75 760,2863.11 760,2910 840,2990 1170,2990 1280,3100 1280,3340 1340,3400 1420,3400 1500,3320 1530,3320 1555.12,3345.12 U4.32@1608.5,3345.12
STATUS_MCU2: R34.1 U4.54 | length 1436
  Top Layer w8: R34.1@902.73,2861.75 920.98,2880 v2(970,2880) ; v2(1270,2880) 1330,2820 1890,2820 v2(1945,2875) ; U4.54@1811.26,3158.11 1811.26,3128.74 v2(1930,3010)
  Bottom Layer w8: v2(970,2880) v2(1270,2880) ; v2(1930,3010) 1945,2995 v2(1945,2875)
SW: C20.2 L1.1 U2.12@3130,2111.02 | length 630.1
  Top Layer w8: C20.2@3010,2102.05 3010,2130 3050,2170 3120,2170 3130,2160 ; U2.12@3130,2111.02 3130,2160 ; L1.1@3530,2190 3160,2190 3130,2160
TCK: J1.9 J1.11 U4.40 | length 2401.1
  Top Layer w8: v2(1410,3270) 1460.87,3219.13 U4.40@1608.5,3219.13
  Bottom Layer w8: v2(1410,3270) 1410,3357.56 1490,3437.56 1990,3437.56 2250,3697.56 2250,3927.56 2190,3987.56 1620,3987.56 1600,3967.56 J1.11@1600,3890 ; J1.11@1600,3867.56 J1.11@1600,3890 ; J1.9@1700,3890 J1.11@1600,3890
TDI: J1.3 U4.42 | length 1931
  Top Layer w8: v2(1360,3230) 1402.36,3187.64 U4.42@1608.5,3187.64
  Bottom Layer w8: v2(1360,3230) 1360,3407.56 1418,3465.56 1978,3465.56 2220,3707.56 2220,3917.56 2180,3957.56 2070,3957.56 2000,3887.56 J1.3@2000,3860
TDO: J1.7 U4.41 | length 2078.5
  Top Layer w8: v2(1410,3230) 1430.2,3230 1456.82,3203.39 U4.41@1608.5,3203.39
  Bottom Layer w8: v2(1410,3230) 1410,3238.18 1387.5,3260.68 1387.5,3402.56 1436.5,3451.56 1984.2,3451.56 2236,3703.36 2236,3921.76 2184.2,3973.56 1883.56,3973.56 J1.7@1800,3890 ; J1.7@1800,3860 J1.7@1800,3863.56
TMS: J1.1 U4.43 | length 1576.3
  Top Layer w8: v2(1460,3110) 1606.94,3110 1638.03,3141.09 U4.43@1638.03,3158.11 ; J1.1@2100,3860 2180,3780 v2(2180,3560)
  POWER w8: v2(1460,3110) 1950,3110 v2(2070,3230)
  Bottom Layer w8: v2(2070,3230) 2070,3450 v2(2180,3560)
TRST: J1.2 U4.6 | length 678.1
  Top Layer w8: U4.6@1872.28,3266.38 1983.62,3266.38 1990,3260 v2(1990,3259.63) ; v2(2096.76,3512.5) 2096.76,3506.76 2100,3510 J1.2@2100,3760
  Bottom Layer w8: v2(1990,3259.63) 1990,3400 2096.76,3506.76 v2(2096.76,3512.5)
VBAT: D12.1 H6.1 Q7.1 Q7.2 Q7.3
VCC: C19.1 U2.5 | length 213.1
  Top Layer w12: C19.1@2970,1896.85 3016.85,1896.85 3109.08,1989.08 U2.5@3109.08,2024.88
VCP: C35.2 R43.1 U3.3 | length 1869.8
  Top Layer w10: C35.2@1440,2480.32 1489.68,2480.32 ; v2(1489.68,2470.32) 1489.68,2480.32 ; U3.3@1563.66,2451.65 1518.35,2451.65 1489.68,2480.32 ; v2(1880,2560) 1940,2620 2170,2620 v2(2510,2960) ; v3(2800,3250) 2802.44,3252.44 R43.1@2802.44,3340
  Bottom Layer w10: v2(1489.68,2470.32) 1579.37,2560 v2(1880,2560) ; v2(2510,2960) v3(2800,3250)
VDD1: C44.1 U4.52 | length 113.1
  Top Layer w8: U4.52@1779.76,3158.11 1779.76,3087.8 C44.1@1810,3057.56
VDD2: C50.1 U4.38 | length 234.2
  Top Layer w8: C50.1@1400,3312.44 1400.06,3312.5 1449.32,3312.5 1511.19,3250.63 U4.38@1608.5,3250.63
VDD3: C47.1 U4.3 | length 118.1
  Top Layer w8: U4.3@1872.28,3219.13 1900.66,3219.13 1949.8,3170 C47.1@1970,3170
VDDA: C51.1 FB2.2 U4.14 | length 132.2
  Top Layer w8: U4.14@1872.28,3392.36 1905.2,3392.36 C51.1@1932.83,3420 1932.83,3479.41 FB2.2@1933.43,3480
VDDIO1: C56.1 FB3.2 U4.26 | length 279.6
  Top Layer w8: FB3.2@1490,3553.43 1490,3502.44 C56.1@1487.56,3500 1527.56,3460 1650,3460 1669.53,3440.47 U4.26@1669.53,3421.89
VDDIO2: C43.1 FB1.2 U4.50 | length 244.7
  Top Layer w8: FB1.2@1686.57,2940 1688.27,2940 1748.27,3000 U4.50@1748.27,3158.11
VDRAIN: NT7.2 U3.5 | length 1336.8
  Top Layer w8: v2@1487.72,2412.28 U3.5@1563.66,2412.28 ; v3(1547.22,1322.57) 1550,1319.79 NT7.2@1550,1300
  POWER w8: v2@1487.72,2417.72 v2@1490,2420
  POWER w20: v2@1487.72,2417.72 1350,2280 1350,1519.79 v3(1547.22,1322.57)
  other v2: 1487.4,2412.6
VM: C7.1 C8.1 C9.1 C10.1 C11.1 C12.1 C13.1 C14.1 C16.1 C21.1 C24.1 C28.1 C29.1 C31.1 C32.1 C33.1 C35.1 C36.1 C38.1 D4.1 D13.3 D15.2 H5.3 L2.2 NT7.1 Q4.5 Q5.5 Q6.5 R8.2 R12.2 R13.2 R31.2 U2.2 U2.9 U2.10 U3.4 VM.1 | length 3909.6
  Top Layer w8: 1550,1274 1570,1254 C9.1@1570,1223.15 C9.1@1563.15,1230
  Top Layer w10: C21.1@2877.56,2110 2877.56,2182.44 C24.1@2885.12,2190 ; D4.1@3690,1371.34 3690,1430 v2(3720,1460)
  Top Layer w12: C38.1@1373.15,2510 1377.56,2505.59 C36.1@1377.56,2430 1435.2,2430 C35.1@1440,2425.2 1446.77,2431.97 1475.66,2431.97 1478.29,2434.6 1496.51,2434.6 1499.14,2431.97 U3.4@1563.66,2431.97 ; v2(3050,2100) 3051.3,2098.7 U2.2@3094.57,2098.7 ; U2.9@3165.43,2072.13 U2.10@3165.43,2098.7 3198.7,2098.7 v2(3200,2100)
  Top Layer w20: C38.1@1373.15,2510 1380,2516.85 v2(1380,2590)
  POWER w20: C11.1@620,1230 620,1240 960,1580 960,2204.88 1345.12,2590 v2(1380,2590) ; v2(1440,1870) 1440,1630 1630,1440 1630,1280
  Bottom Layer w10: v2(3720,1460) 3790,1530 3790,2050 v2(3730,2110)
  Bottom Layer w20: D15.2@1370,1944.41 1405.59,1944.41 1440,1910 v2(1440,1870)
  other v2: 2950,2260 2950,2310 2950,2360 2950,2410 2950,2460 2670,2490 2740,2490 2810,2490 2880,2490 3030,2490 3100,2490 3170,2490 3240,2490
  other v3: 2420,310 2510,310 2420,390 2510,390 2420,470 2510,470 520,880 600,880 520,930 600,930 520,980 600,980 3100,1060 3170,1060 540,1110 610,1110 3100,1110 3170,1110 2810,1120 2920,1120 1920,1150 2000,1150 3100,1160 3170,1160 490,1170 570,1170 1670,1170 1760,1170 1920,1200 2000,1200 2860,1220 450,1230 530,1230 1670,1240 1760,1240 1920,1250 2000,1250 2687.5,1282.5 1670,1320 1760,1320 2620,1340 2560,1400
VSDO: NT17.2 U3.40 | length 38
  Top Layer w8: U3.40@1779.21,2549.09 1779.21,2585.97 1780,2586.76
VSEN_A: C53.1 R5.1 R45.2 U4.9 | length 4232.1
  Top Layer w8: R5.1@1087.56,650 v3(1170,650) ; U4.9@1872.28,3313.62 2076.38,3313.62 2090,3300 2120,3300 2210,3390 2259.37,3390 2313.94,3444.57 R45.2@2360,3444.56 2360,3420 v2(2330,3390)
  POWER w8: v2(2250,3140) 2330,3220 v2(2330,3390)
  Bottom Layer w8: v3(1170,650) 1250,730 1250,1480 1470,1700 1890,1700 2317.5,2127.5 2317.5,2399.32 2326,2407.82 2326,3056 2250,3132 v2(2250,3140)
VSEN_B: C54.1 R10.1 R46.2 U4.8 | length 3388.7
  Top Layer w8: U4.8@1872.28,3297.87 2072.33,3297.87 2084.2,3286 2125.8,3286 2209.8,3370 2345.43,3370 R46.2@2420,3444.57 2423.94,3440.63 C54.1@2460,3440.63 2460,3440 v3(2410,3390) ; R10.1@2115.12,900 2150,900 v2(2160,910) ; v2(2280,2040) v2(2280,2140)
  POWER w8: v2(2250,3100) 2410,3260 v3(2410,3390)
  Bottom Layer w8: v2(2160,910) 2160,1920 v2(2280,2040) ; v2(2250,3100) 2280,3070 v2(2280,2140)
VSEN_CH: C55.1 R9.1 R47.2 U4.7 | length 4387.8
  Top Layer w8: U4.7@1872.28,3282.13 2068.28,3282.13 2078.4,3272 2131.6,3272 2141.72,3282.13 2142.13,3282.13 2216,3356 2429.94,3356 C55.1@2520,3446.06 2556.06,3446.06 R47.2@2560,3450 2560,3170 v3(2440,3050) ; v2(2320,1210) 2320,710 v3(2360,670) ; v3(2980,730) 2980,777.56 R9.1@3002.44,800
  Bottom Layer w8: v2(2320,1210) 2317.5,1212.5 2317.5,2047.5 2440,2170 v3(2440,3050) ; v3(2360,670) 2420,730 v3(2980,730)
VSEN_CL: C52.1 R3.1 R44.2 U4.21 | length 3739.4
  Top Layer w8: v2(1700,3520) 1700,3500 1748.27,3451.73 U4.21@1748.27,3421.89 ; v2(2180,3440) 2215.75,3440 2220,3444.25 2256.06,3444.25 C52.1@2259.84,3440.47 ; v2(2350,1200) 2350,720 2392.44,677.56 R3.1@2392.44,620
  POWER w8: v2(1700,3520) 1700,3490 1750,3440 v2(2180,3440)
  Bottom Layer w8: v2(2180,3440) 2370,3250 2445.1,3174.9 2470,3150 2470,2090 2370,1990 2370,1220 v2(2350,1200)
VSEN_VM: C42.1 R31.1 R32.2 U4.10 | length 1290.2
  Top Layer w8: U4.10@1872.28,3329.37 2090.63,3329.37 v2(2100,3320) ; v2(2330,3090) 2400,3020 2492.44,3020 C42.1@2600,2912.44 2592.44,2912.44 2540,2860 2540,2707.56 R31.1@2590,2657.56 R32.2@2590,2742.44
  Bottom Layer w8: v2(2100,3320) v2(2330,3090)
pads on no net: H3.1 H4.1 H7.1 H8.1 H9.0 H10.0 H11.0 H12.0 J1.6 J1.13 J1.14 U1.5 U1.7@2790,1910 U1.7@2825.43,1910 U2.3 U2.8 U2.12@3130,2091.02 U2.12@3130,2130.98 U3.48 U3.49@1730,2382.76 U4.35

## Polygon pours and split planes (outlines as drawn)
6V_BUCK on Top Layer "6V_BUCK_L01_P048" (solid, remove dead copper, pour order 48): 2750,1887.22 2828.74,1887.22 2828.74,1800 2930,1800 2930,1540 2750,1540
NetC50_2 on Top Layer "NETC50_2_L01_P050" (solid, remove dead copper, pour order 50): 1200,1080 800,1080 800,970 1000,970 1000,900 997.71,902.29 960,902.29 960,680 1200,680 1200,900
no net on Top Layer "NONET_L01_P142" (solid, remove dead copper, pour order 142): 800,1020
NetC51_2 on Top Layer "NETC51_2_L01_P200" (solid, remove dead copper, pour order 200): 2480,910 2480,820 2650,820 2650,640 2880,640 2880,670 2960,670 2950,680 2950,880 2710,880 2710,910
GND on Top Layer "GND_L01_P074" (solid, remove dead copper, pour order 74): 2990,2260 2990,2390 2995.81,2394.19 3322.73,2394.19 3322.73,2262.73 3320,2260
GND on Top Layer "GND_L01_P198" (solid, remove dead copper, pour order 198): 1730,2840.91 1730,2970 1780,2970 1780,3030 1839.47,3030 1840,3000 1880,3000 1880,2840
VM on Top Layer "VM_L01_P118" (solid, remove dead copper, pour order 118): 2430,1530 2430,1380 2760,1050 2860,1050 2920,990 3020,990 3020,1010 3250,1010 3250,1290 2760,1290 2520,1530
GND on Top Layer "GND_L01_P218" (solid, remove dead copper, pour order 218): -16.99,-19.93 3843.01,-19.93 3843.01,3980.07 -16.99,3980.07
VM on Top Layer "VM_L01_P110" (solid, remove dead copper, pour order 110): 2473.07,2856.49 3833.07,2856.49 3833.07,2036.49 2853.07,2036.49 2853.07,2156.49 2643.07,2156.49 2643.07,2326.49 2473.07,2326.49
GND on Top Layer "GND_L01_P214" (solid, remove dead copper, pour order 214): 3300,520 3440,520 3440,690 3300,690
NetC52_2 on Top Layer "NETC52_2_L01_P210" (solid, remove dead copper, pour order 210): 1700,820 1700,590 1410,590 1410,820
OUT_C1 on Top Layer "OUT_C1_L01_P208" (solid, remove dead copper, pour order 208): 3300,260 3300,700 3300,878.63 3180,879.89 3180,1000 3040,1000 3040,440 2930,440 2930,260
OUT_C2 on Top Layer "OUT_C2_L01_P194" (solid, remove dead copper, pour order 194): -200,-30
OUT_C2 on Top Layer "OUT_C2_L01_P190" (solid, remove dead copper, pour order 190): 2930,260 2930,440 2950,440 2950,580 2880,580 2880,640 2650,640 2650,820 2420,820 2420,530 2610,530 2610,260
OUT_B1 on Top Layer "OUT_B1_L01_P188" (solid, remove dead copper, pour order 188): 2330,260 2330,565 2200,565 2200,875 2090,875 2090,1095 1860,1095 1860,795 1990,795 1990,260
OUT_B2 on Top Layer "OUT_B2_L01_P184" (solid, remove dead copper, pour order 184): 1980,260 1980,520 1980,800 1934.29,840 1740,840 1740,850 1700,850 1700,260
VM on Top Layer "VM_L01_P168" (solid, remove dead copper, pour order 168): 1510,1360 2160,1360 2160,1110 1510,1110
OUT_A1 on Top Layer "OUT_A1_L01_P164" (solid, remove dead copper, pour order 164): 670,980 740,980 740,1020 800,1020 800,970 1070,970 1070,610 1070,260 790,260 790,470 670,470
VM on Top Layer "VM_L01_P144" (solid, remove dead copper, pour order 144): 650,1260 650,730 590,730 590,770 410,770 400,770 400,1260
VBAT on Top Layer "VBAT_L01_P138" (solid, remove dead copper, pour order 138): 3130,3310 3550,3310 3550,3520 3550,3970 3130,3970
NetC15_1 on Top Layer "NETC15_1_L01_P108" (solid, remove dead copper, pour order 108): 3220,3300 3600,3300 3600,2760 3520,2760 3520,2570 3220,2570 3220,2770 2700,2770 2700,3190 3220,3190
6V_BUCK on Top Layer "6V_BUCK_L01_P096" (solid, remove dead copper, pour order 96): 3630,1910 3630,1320 2930,1320 2930,1910
3.3V_LDO on POWER "3.3V_LDO" (solid, remove dead copper, pour order 124): 370,3960 2340,3960 2340,2300 2340,2100 2720,2100 2720,1990 2890,1990 2890,1820 2460,1820 2000,1820 2000,2180 2000,2320 370,2320
VM on POWER "VM_L02_P216" (solid, remove dead copper, pour order 216): 3500,2030 3500,1380 370,1380 370,240 3830,240 3830,2030
VM on POWER "VM_L02_P112" (solid, remove dead copper, pour order 112): 2470,2850 3830,2850 3830,2030 2850,2030 2850,2150 2640,2150 2640,2320 2470,2320
6V_BUCK on POWER "6V_BUCK_L02_P140" (solid, remove dead copper, pour order 140): 3500,1910 3500,1320 2930,1320 2930,1910
VBAT on POWER "VBAT_L02_P134" (solid, remove dead copper, pour order 134): 3130,3310 3550,3310 3550,3520 3550,3970 3130,3970
GND on GND "GND_L03_P220" (solid, remove dead copper, pour order 220): 0,4000 3860,4000 3860,0 0,0
VM on Bottom Layer "VM_L04_P034" (solid, remove dead copper, pour order 34): 2900,500 2990,500 2990,709.79 2630,709.79 2630,640 2350,640 2350,500 2350,260 2590,260 2590,500
GND on Bottom Layer "GND_L04_P170" (solid, remove dead copper, pour order 170): 1580,2510 1580,2260 1640,2260 1640,2220 1860,2220 1860,2510
OUT_C1 on Bottom Layer "OUT_C1_L04_P206" (solid, remove dead copper, pour order 206): 3300,710 3300,260 2930,260 2930,440 3040,440 3040,710
OUT_C2 on Bottom Layer "OUT_C2_L04_P154" (solid, remove dead copper, pour order 154): 2650,500 2900,500 2900,260 2640,260 2640,500
GND on Bottom Layer "GND_L04_P222" (solid, remove dead copper, pour order 222): 0,4000 3860,4000 3860,0 0,0

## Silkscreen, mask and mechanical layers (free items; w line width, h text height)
Top Overlay:
  lines w10: 360,3710 360,3750 389.63,3779.63 ; 2950,580 2970,580 2990,600 ; 2990,1710 3120,1710 3140,1730 ; 640,2950 640,3230 1180,3230 1180,2950 640,2950 ; 670,2260 670,2700 1130,2700 1130,2260 670,2260 ; 2480,2160 2640,2160 2640,2370 2480,2370 2480,2160 ; 3260,1560 3410,1560 3410,1770 3260,1770 3260,1560 ; 3380,1110 3750,1110 3750,1480 3380,1480 3380,1110 ; 3480,2220 3480,2400 3760,2400 3760,2220 3480,2220
  text "JTAG" at 2210,3830 h72.83
  text "POT" at 660,3720 h72.83
  text "OPEN LD" at 1280,3670 h72.83 r90
  text "DETECT" at 1340,3670 h72.83 r90
  text "RST" at 340,3650 h72.83
  text "GND" at 2500,3590 h72.83
  text "VBAT" at 3500,3560 h72.83
  text "PB_A" at 360,3460 h72.83
  text "A" at 690,2990 h72.83
  text "B" at 820,2990 h72.83
  text "CH" at 930,2990 h72.83
  text "CL" at 1080,2990 h72.83
  text "PB_B" at 360,2890 h72.83
  text "MCU1" at 740,2520 h72.83 r270
  text "MCU2" at 880,2520 h72.83 r270
  text "nFAULT" at 1020,2520 h72.83 r270
  text "PB_CH" at 380,2350 h72.83
  text "STATUS LEDS" at 690,2170 h72.83
  text "PB_CL" at 370,1740 h72.83
  text "3.3" at 3410,1410 h72.83
  text "6V" at 3530,1410 h72.83
  text "VM" at 3640,1410 h72.83
  text "SYSTEM LEDS" at 3350,1040 h72.83
  text "GND" at 540,560 h72.83
  text "OUT_CL" at 2620,560 h72.83
  text "OUT_CH" at 3030,560 h72.83
  text "OUT_A" at 880,550 h72.83
  text "OUT_BL" at 1760,550 h72.83
  text "OUT_BH" at 2080,550 h72.83
  text "VM" at 1320,540 h72.83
